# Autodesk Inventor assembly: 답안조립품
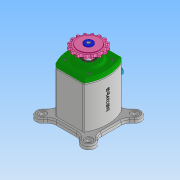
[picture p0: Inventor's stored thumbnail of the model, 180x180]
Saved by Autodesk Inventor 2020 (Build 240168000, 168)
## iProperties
Created: 2022-01
Part Number: 답안조립품
Document SubType Name: Assembly
Designer: user
Author: user
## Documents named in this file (13)
- C:\Users\user\Desktop\720117V1014\답안조립품.iam
- C:\Users\user\Desktop\720117V1014\베어링 6203.ipt
- C:\Users\user\Desktop\720117V1014\본체.ipt
- C:\Users\user\Desktop\720117V1014\볼트 M4 x 12.ipt
- C:\Users\user\Desktop\720117V1014\부시.ipt
- C:\Users\user\Desktop\720117V1014\스프로킷.ipt
- C:\Users\user\Desktop\720117V1014\슬라이더.ipt
- C:\Users\user\Desktop\720117V1014\오일 실 17 x 30 x 8.ipt
- C:\Users\user\Desktop\720117V1014\와셔 4 x 20.ipt
- C:\Users\user\Desktop\720117V1014\육각머리볼트 M4.ipt
- C:\Users\user\Desktop\720117V1014\커버.ipt
- C:\Users\user\Desktop\720117V1014\키 5 x 5.ipt
- C:\Users\user\Desktop\720117V1014\편심축.ipt
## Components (8 placed, 1 different names)
1. M4x0.7x12:1
2. M4x0.7x12:2
3. M4x0.7x12:3
4. M4x0.7x12:4
5. M4x0.7x12:5
6. M4x0.7x12:6
7. M4x0.7x12:7
8. M4x0.7x12:8
